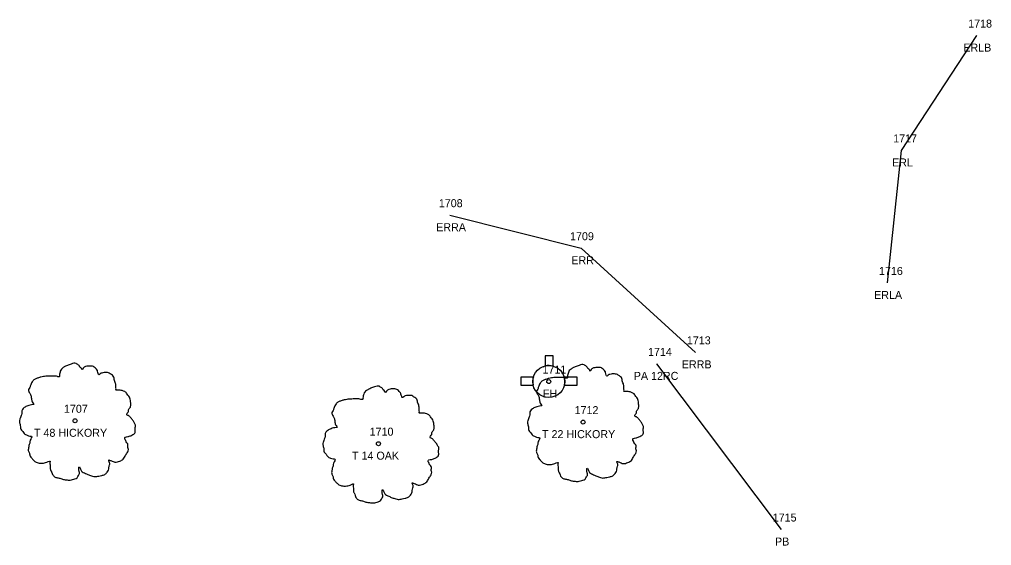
# Model space of a CAD drawing. Extents: x 1965822 to 1970313, y 1117097 to 1118160.
# Drawn here: x 1966667.7 to 1966789.1, y 1117381.5 to 1117447.2 of the extents above; entities that cross this region are included whole.
import ezdxf

# ---------------------------------------------------------------- set-up
doc = ezdxf.new("R2010")
doc.units = 0
for name, color, linetype in [('RD_EX_DR_Pipe', 7, 'Continuous'), ('RD_EX_DR_Pipe_txCode', 7, 'Continuous'), ('RD_EX_Road', 7, 'Continuous'), ('RD_EX_Road_txCode', 7, 'Continuous'), ('RD_EX_UT', 7, 'Continuous'), ('RD_EX_UT_txCode', 7, 'Continuous'), ('RD_EX_VEG', 7, 'Continuous'), ('RD_EX_VEG_txCode', 7, 'Continuous'), ('RD_SMD_Locator', 7, 'Continuous')]:
    doc.layers.add(name, color=color, linetype=linetype)

msp = doc.modelspace()

# ---------------------------------------------------------------- linework, layer by layer
at = {"layer": 'RD_EX_DR_Pipe'}
msp.add_line((1966747.3, 1117404.17), (1966762.88, 1117383.47), dxfattribs=at)
at = {"layer": 'RD_EX_Road'}
for points in [[(1966776.17, 1117414.28), (1966777.92, 1117430.84), (1966787.3, 1117445.19)], [(1966721.5, 1117422.75), (1966737.88, 1117418.62), (1966752.16, 1117405.61)]]:
    msp.add_lwpolyline(points, dxfattribs=at)
at = {"layer": 'RD_EX_UT'}
for p, q in [((1966733.38, 1117405.18), (1966733.38, 1117403.91)), ((1966734.38, 1117405.18), (1966733.38, 1117405.18)), ((1966734.38, 1117403.88), (1966734.38, 1117405.18)), ((1966731.92, 1117402.53), (1966730.37, 1117402.53)), ((1966730.37, 1117402.53), (1966730.37, 1117401.53)), ((1966737.37, 1117402.53), (1966735.76, 1117402.53)), ((1966737.37, 1117401.53), (1966737.37, 1117402.53)), ((1966730.37, 1117401.53), (1966731.89, 1117401.53)), ((1966735.79, 1117401.53), (1966737.37, 1117401.53))]:
    msp.add_line(p, q, dxfattribs=at)
for radius in [2, 0.25]:
    msp.add_circle((1966733.84, 1117401.96), radius, dxfattribs=at)
for start, end in [(74.2455, 103.2128), (163.3387, 192.315), (347.685, 16.6613)]:
    msp.add_arc((1966733.84, 1117401.96), 2, start, end, dxfattribs=at)
at = {"layer": 'RD_EX_VEG'}
for centre, radius in [((1966674.67, 1117397.06), 0.25), ((1966674.66, 1117397.04), 0.0001), ((1966738.13, 1117396.89), 0.25), ((1966738.12, 1117396.87), 0.0001), ((1966712.57, 1117394.2), 0.25), ((1966712.56, 1117394.18), 0.0001)]:
    msp.add_circle(centre, radius, dxfattribs=at)
for points in [[(1966674.81, 1117404.23), (1966674.51, 1117404.25), (1966674.18, 1117404.15), (1966673.93, 1117404.05), (1966673.71, 1117403.98), (1966673.48, 1117403.88), (1966673.18, 1117403.7), (1966672.96, 1117403.5), (1966672.83, 1117403.25), (1966672.78, 1117403.03), (1966672.73, 1117402.75), (1966672.73, 1117402.58), (1966672.61, 1117402.55), (1966672.46, 1117402.58), (1966672.21, 1117402.65), (1966671.96, 1117402.65), (1966671.71, 1117402.65), (1966671.36, 1117402.63), (1966671.01, 1117402.63), (1966670.73, 1117402.58), (1966670.41, 1117402.53), (1966670.03, 1117402.4), (1966669.68, 1117402.28), (1966669.38, 1117402.03), (1966669.13, 1117401.55), (1966669.01, 1117401.2), (1966668.86, 1117400.95), (1966669.01, 1117400.5), (1966669.18, 1117400.15), (1966669.21, 1117399.95), (1966669.28, 1117399.53), (1966669.38, 1117399.3), (1966669.51, 1117399.1), (1966669.43, 1117399.08), (1966669.06, 1117399.03), (1966668.76, 1117398.93), (1966668.33, 1117398.7), (1966668.11, 1117398.48), (1966668.01, 1117398.15), (1966667.98, 1117397.8), (1966667.88, 1117397.6), (1966667.81, 1117397.33), (1966667.78, 1117397.25), (1966667.73, 1117396.93), (1966667.83, 1117396.48), (1966667.86, 1117396.13), (1966667.98, 1117395.9), (1966668.13, 1117395.73), (1966668.31, 1117395.48), (1966668.71, 1117395.25), (1966669.03, 1117395.15), (1966669.23, 1117395.13), (1966669.06, 1117394.63), (1966669.01, 1117394.28), (1966668.88, 1117393.88), (1966668.88, 1117393.81), (1966668.83, 1117393.33), (1966668.98, 1117393.01), (1966669.06, 1117392.63), (1966669.23, 1117392.41), (1966669.51, 1117392.11), (1966669.83, 1117391.88), (1966670.33, 1117391.76), (1966670.73, 1117391.78), (1966671.31, 1117391.96), (1966671.56, 1117392.03), (1966671.53, 1117391.86), (1966671.56, 1117391.48), (1966671.56, 1117391.06), (1966671.71, 1117390.73), (1966671.81, 1117390.46), (1966671.96, 1117390.21), (1966672.28, 1117389.98), (1966672.68, 1117389.91), (1966673.11, 1117389.76), (1966673.56, 1117389.68), (1966674.06, 1117389.66), (1966674.66, 1117389.81), (1966674.93, 1117389.93), (1966675.03, 1117390.11), (1966675.23, 1117390.48), (1966675.18, 1117390.71), (1966675.21, 1117391.31), (1966675.31, 1117391.13), (1966675.48, 1117390.78), (1966675.98, 1117390.48), (1966676.38, 1117390.31), (1966676.86, 1117390.16), (1966677.16, 1117390.08), (1966677.63, 1117390.16), (1966678.01, 1117390.23), (1966678.38, 1117390.36), (1966678.68, 1117390.63), (1966678.85, 1117390.91), (1966678.9, 1117391.18), (1966678.98, 1117391.56), (1966679.03, 1117391.73)], [(1966679.03, 1117391.73), (1966678.95, 1117391.91), (1966678.9, 1117392.16), (1966678.98, 1117392.13), (1966679.15, 1117392.08), (1966679.43, 1117391.96), (1966679.65, 1117391.88), (1966679.98, 1117391.91), (1966680.25, 1117392.01), (1966680.7, 1117392.28), (1966680.98, 1117392.76), (1966681.25, 1117393.16), (1966681.33, 1117393.48), (1966681.28, 1117393.71), (1966681.25, 1117394.2), (1966681.05, 1117394.45), (1966681, 1117394.58), (1966680.9, 1117394.98), (1966680.98, 1117395.03), (1966681.25, 1117395.08), (1966681.63, 1117395.2), (1966681.9, 1117395.33), (1966682.13, 1117395.5), (1966682.2, 1117395.73), (1966682.18, 1117396.13), (1966682.23, 1117396.53), (1966682.15, 1117396.68), (1966682.05, 1117396.83), (1966681.98, 1117397.03), (1966681.83, 1117397.18), (1966681.73, 1117397.33), (1966681.63, 1117397.43), (1966681.5, 1117397.58), (1966681.33, 1117397.7), (1966681.18, 1117397.75), (1966681.13, 1117397.9), (1966681.28, 1117398.1), (1966681.33, 1117398.2), (1966681.35, 1117398.43), (1966681.58, 1117398.78), (1966681.63, 1117399.18), (1966681.58, 1117399.6), (1966681.53, 1117399.88), (1966681.38, 1117400.15), (1966681.18, 1117400.4), (1966681.05, 1117400.58), (1966680.88, 1117400.7), (1966680.55, 1117400.83), (1966680.3, 1117400.88), (1966679.95, 1117400.88), (1966679.75, 1117400.93), (1966679.78, 1117400.98), (1966679.78, 1117401.13), (1966679.78, 1117401.4), (1966679.7, 1117401.85), (1966679.55, 1117402.35), (1966679.55, 1117402.38), (1966679.45, 1117402.63), (1966679.23, 1117402.83), (1966679.05, 1117402.93), (1966678.85, 1117403.05), (1966678.6, 1117403.08), (1966678.3, 1117403.08), (1966678.03, 1117403.03), (1966677.83, 1117402.93), (1966677.66, 1117402.8), (1966677.58, 1117402.95), (1966677.48, 1117403.25), (1966677.43, 1117403.4), (1966677.28, 1117403.58), (1966677.06, 1117403.78), (1966676.61, 1117403.9), (1966675.98, 1117403.83), (1966675.68, 1117403.63), (1966675.53, 1117403.45), (1966675.48, 1117403.58), (1966675.28, 1117403.78), (1966675.18, 1117403.95), (1966675.01, 1117404.08), (1966674.86, 1117404.18), (1966674.76, 1117404.23)], [(1966738.26, 1117404.06), (1966737.96, 1117404.08), (1966737.64, 1117403.98), (1966737.39, 1117403.88), (1966737.16, 1117403.81), (1966736.94, 1117403.71), (1966736.64, 1117403.53), (1966736.41, 1117403.33), (1966736.29, 1117403.08), (1966736.24, 1117402.86), (1966736.19, 1117402.58), (1966736.19, 1117402.41), (1966736.06, 1117402.38), (1966735.91, 1117402.41), (1966735.66, 1117402.48), (1966735.41, 1117402.48), (1966735.16, 1117402.48), (1966734.81, 1117402.46), (1966734.46, 1117402.46), (1966734.19, 1117402.41), (1966733.86, 1117402.36), (1966733.49, 1117402.23), (1966733.14, 1117402.11), (1966732.84, 1117401.86), (1966732.59, 1117401.38), (1966732.46, 1117401.03), (1966732.31, 1117400.78), (1966732.46, 1117400.33), (1966732.64, 1117399.99), (1966732.66, 1117399.79), (1966732.74, 1117399.36), (1966732.84, 1117399.14), (1966732.96, 1117398.94), (1966732.89, 1117398.91), (1966732.51, 1117398.86), (1966732.21, 1117398.76), (1966731.79, 1117398.54), (1966731.56, 1117398.31), (1966731.46, 1117397.99), (1966731.44, 1117397.64), (1966731.34, 1117397.44), (1966731.26, 1117397.16), (1966731.24, 1117397.09), (1966731.19, 1117396.76), (1966731.29, 1117396.31), (1966731.31, 1117395.96), (1966731.44, 1117395.74), (1966731.59, 1117395.56), (1966731.76, 1117395.31), (1966732.16, 1117395.09), (1966732.49, 1117394.99), (1966732.69, 1117394.96), (1966732.51, 1117394.46), (1966732.46, 1117394.11), (1966732.34, 1117393.71), (1966732.34, 1117393.64), (1966732.29, 1117393.16), (1966732.44, 1117392.84), (1966732.51, 1117392.46), (1966732.69, 1117392.24), (1966732.96, 1117391.94), (1966733.29, 1117391.71), (1966733.79, 1117391.59), (1966734.19, 1117391.61), (1966734.76, 1117391.79), (1966735.01, 1117391.86), (1966734.99, 1117391.69), (1966735.01, 1117391.31), (1966735.01, 1117390.89), (1966735.16, 1117390.56), (1966735.26, 1117390.29), (1966735.41, 1117390.04), (1966735.74, 1117389.81), (1966736.14, 1117389.74), (1966736.56, 1117389.59), (1966737.01, 1117389.51), (1966737.51, 1117389.49), (1966738.11, 1117389.64), (1966738.39, 1117389.76), (1966738.49, 1117389.94), (1966738.69, 1117390.31), (1966738.64, 1117390.54), (1966738.66, 1117391.14), (1966738.76, 1117390.96), (1966738.94, 1117390.61), (1966739.44, 1117390.31), (1966739.84, 1117390.14), (1966740.31, 1117389.99), (1966740.61, 1117389.91), (1966741.08, 1117389.99), (1966741.46, 1117390.06), (1966741.83, 1117390.19), (1966742.13, 1117390.46), (1966742.31, 1117390.74), (1966742.36, 1117391.01), (1966742.43, 1117391.39), (1966742.48, 1117391.56)], [(1966742.48, 1117391.56), (1966742.41, 1117391.74), (1966742.36, 1117391.99), (1966742.43, 1117391.96), (1966742.61, 1117391.91), (1966742.88, 1117391.79), (1966743.11, 1117391.71), (1966743.43, 1117391.74), (1966743.71, 1117391.84), (1966744.16, 1117392.11), (1966744.43, 1117392.59), (1966744.71, 1117392.99), (1966744.78, 1117393.31), (1966744.73, 1117393.54), (1966744.71, 1117394.04), (1966744.51, 1117394.29), (1966744.46, 1117394.41), (1966744.36, 1117394.81), (1966744.43, 1117394.86), (1966744.71, 1117394.91), (1966745.08, 1117395.04), (1966745.36, 1117395.16), (1966745.58, 1117395.34), (1966745.66, 1117395.56), (1966745.63, 1117395.96), (1966745.68, 1117396.36), (1966745.61, 1117396.51), (1966745.51, 1117396.66), (1966745.43, 1117396.86), (1966745.28, 1117397.01), (1966745.18, 1117397.16), (1966745.08, 1117397.26), (1966744.96, 1117397.41), (1966744.78, 1117397.54), (1966744.63, 1117397.59), (1966744.58, 1117397.74), (1966744.73, 1117397.94), (1966744.78, 1117398.04), (1966744.81, 1117398.26), (1966745.03, 1117398.61), (1966745.08, 1117399.01), (1966745.03, 1117399.44), (1966744.98, 1117399.71), (1966744.83, 1117399.99), (1966744.63, 1117400.23), (1966744.51, 1117400.41), (1966744.33, 1117400.53), (1966744.01, 1117400.66), (1966743.76, 1117400.71), (1966743.41, 1117400.71), (1966743.21, 1117400.76), (1966743.23, 1117400.81), (1966743.23, 1117400.96), (1966743.23, 1117401.23), (1966743.16, 1117401.68), (1966743.01, 1117402.18), (1966743.01, 1117402.21), (1966742.91, 1117402.46), (1966742.68, 1117402.66), (1966742.51, 1117402.76), (1966742.31, 1117402.88), (1966742.06, 1117402.91), (1966741.76, 1117402.91), (1966741.48, 1117402.86), (1966741.28, 1117402.76), (1966741.11, 1117402.63), (1966741.03, 1117402.78), (1966740.93, 1117403.08), (1966740.88, 1117403.23), (1966740.73, 1117403.41), (1966740.51, 1117403.61), (1966740.06, 1117403.73), (1966739.44, 1117403.66), (1966739.14, 1117403.46), (1966738.99, 1117403.28), (1966738.94, 1117403.41), (1966738.74, 1117403.61), (1966738.64, 1117403.78), (1966738.46, 1117403.91), (1966738.31, 1117404.01), (1966738.21, 1117404.06)], [(1966712.7, 1117401.37), (1966712.4, 1117401.4), (1966712.08, 1117401.3), (1966711.83, 1117401.2), (1966711.6, 1117401.12), (1966711.38, 1117401.02), (1966711.08, 1117400.85), (1966710.85, 1117400.65), (1966710.73, 1117400.4), (1966710.68, 1117400.17), (1966710.63, 1117399.9), (1966710.63, 1117399.72), (1966710.5, 1117399.7), (1966710.35, 1117399.72), (1966710.1, 1117399.8), (1966709.85, 1117399.8), (1966709.6, 1117399.8), (1966709.25, 1117399.77), (1966708.9, 1117399.77), (1966708.63, 1117399.72), (1966708.3, 1117399.67), (1966707.93, 1117399.55), (1966707.58, 1117399.42), (1966707.28, 1117399.17), (1966707.03, 1117398.7), (1966706.9, 1117398.35), (1966706.75, 1117398.1), (1966706.9, 1117397.65), (1966707.08, 1117397.3), (1966707.1, 1117397.1), (1966707.18, 1117396.67), (1966707.28, 1117396.45), (1966707.4, 1117396.25), (1966707.33, 1117396.22), (1966706.95, 1117396.17), (1966706.65, 1117396.07), (1966706.23, 1117395.85), (1966706, 1117395.62), (1966705.9, 1117395.3), (1966705.88, 1117394.95), (1966705.78, 1117394.75), (1966705.7, 1117394.47), (1966705.68, 1117394.4), (1966705.63, 1117394.07), (1966705.73, 1117393.62), (1966705.75, 1117393.27), (1966705.88, 1117393.05), (1966706.03, 1117392.87), (1966706.2, 1117392.62), (1966706.6, 1117392.4), (1966706.93, 1117392.3), (1966707.13, 1117392.27), (1966706.95, 1117391.77), (1966706.9, 1117391.42), (1966706.78, 1117391.02), (1966706.78, 1117390.95), (1966706.73, 1117390.48), (1966706.88, 1117390.15), (1966706.95, 1117389.78), (1966707.13, 1117389.55), (1966707.4, 1117389.25), (1966707.73, 1117389.03), (1966708.23, 1117388.9), (1966708.63, 1117388.93), (1966709.2, 1117389.1), (1966709.45, 1117389.18), (1966709.43, 1117389), (1966709.45, 1117388.63), (1966709.45, 1117388.2), (1966709.6, 1117387.88), (1966709.7, 1117387.6), (1966709.85, 1117387.35), (1966710.18, 1117387.13), (1966710.58, 1117387.05), (1966711, 1117386.9), (1966711.45, 1117386.83), (1966711.95, 1117386.8), (1966712.55, 1117386.95), (1966712.83, 1117387.08), (1966712.93, 1117387.25), (1966713.12, 1117387.63), (1966713.07, 1117387.85), (1966713.1, 1117388.45), (1966713.2, 1117388.28), (1966713.37, 1117387.93), (1966713.87, 1117387.63), (1966714.27, 1117387.45), (1966714.75, 1117387.3), (1966715.05, 1117387.23), (1966715.52, 1117387.3), (1966715.9, 1117387.38), (1966716.27, 1117387.5), (1966716.57, 1117387.78), (1966716.75, 1117388.05), (1966716.8, 1117388.33), (1966716.87, 1117388.7), (1966716.92, 1117388.88)], [(1966716.92, 1117388.88), (1966716.85, 1117389.05), (1966716.8, 1117389.3), (1966716.87, 1117389.28), (1966717.05, 1117389.23), (1966717.32, 1117389.1), (1966717.55, 1117389.03), (1966717.87, 1117389.05), (1966718.15, 1117389.15), (1966718.6, 1117389.43), (1966718.87, 1117389.9), (1966719.15, 1117390.3), (1966719.22, 1117390.63), (1966719.17, 1117390.85), (1966719.15, 1117391.35), (1966718.95, 1117391.6), (1966718.9, 1117391.72), (1966718.8, 1117392.12), (1966718.87, 1117392.17), (1966719.15, 1117392.22), (1966719.52, 1117392.35), (1966719.8, 1117392.47), (1966720.02, 1117392.65), (1966720.1, 1117392.87), (1966720.07, 1117393.27), (1966720.12, 1117393.67), (1966720.05, 1117393.82), (1966719.95, 1117393.97), (1966719.87, 1117394.17), (1966719.72, 1117394.32), (1966719.62, 1117394.47), (1966719.52, 1117394.57), (1966719.4, 1117394.72), (1966719.22, 1117394.85), (1966719.07, 1117394.9), (1966719.02, 1117395.05), (1966719.17, 1117395.25), (1966719.22, 1117395.35), (1966719.25, 1117395.57), (1966719.47, 1117395.92), (1966719.52, 1117396.32), (1966719.47, 1117396.75), (1966719.42, 1117397.02), (1966719.27, 1117397.3), (1966719.07, 1117397.55), (1966718.95, 1117397.72), (1966718.77, 1117397.85), (1966718.45, 1117397.97), (1966718.2, 1117398.02), (1966717.85, 1117398.02), (1966717.65, 1117398.07), (1966717.67, 1117398.12), (1966717.67, 1117398.27), (1966717.67, 1117398.55), (1966717.6, 1117399), (1966717.45, 1117399.5), (1966717.45, 1117399.52), (1966717.35, 1117399.77), (1966717.12, 1117399.97), (1966716.95, 1117400.07), (1966716.75, 1117400.2), (1966716.5, 1117400.22), (1966716.2, 1117400.22), (1966715.92, 1117400.17), (1966715.72, 1117400.07), (1966715.55, 1117399.95), (1966715.47, 1117400.1), (1966715.37, 1117400.4), (1966715.32, 1117400.55), (1966715.17, 1117400.72), (1966714.95, 1117400.92), (1966714.5, 1117401.05), (1966713.87, 1117400.97), (1966713.57, 1117400.77), (1966713.42, 1117400.6), (1966713.37, 1117400.72), (1966713.17, 1117400.92), (1966713.07, 1117401.1), (1966712.9, 1117401.22), (1966712.75, 1117401.32), (1966712.65, 1117401.37)]]:
    msp.add_spline(points, degree=3, dxfattribs=at)
at = {"layer": 'RD_SMD_Locator'}
for centre in [(1966787.3, 1117445.19), (1966777.92, 1117430.84), (1966721.5, 1117422.75), (1966737.88, 1117418.62), (1966776.17, 1117414.28), (1966752.16, 1117405.61), (1966747.3, 1117404.17), (1966762.88, 1117383.47)]:
    msp.add_circle(centre, 0.001, dxfattribs=at)

# ---------------------------------------------------------------- texts
at = {"layer": 'RD_EX_DR_Pipe_txCode'}
for s, p in [('1714', (1966746.24, 1117405.17)), ('PA 12RC', (1966744.46, 1117402.17)), ('1715', (1966761.82, 1117384.47)), ('PB', (1966762.1, 1117381.47))]:
    msp.add_text(s, height=1, dxfattribs=at).set_placement(p)
at = {"layer": 'RD_EX_Road_txCode'}
for s, p in [('1718', (1966786.23, 1117446.19)), ('ERLB', (1966785.62, 1117443.19)), ('1717', (1966776.86, 1117431.84)), ('ERL', (1966776.72, 1117428.84)), ('1708', (1966720.11, 1117423.75)), ('ERRA', (1966719.78, 1117420.75)), ('1709', (1966736.5, 1117419.62)), ('ERR', (1966736.66, 1117416.62)), ('1716', (1966775.09, 1117415.28)), ('ERLA', (1966774.48, 1117412.28)), ('1713', (1966751.09, 1117406.61)), ('ERRB', (1966750.46, 1117403.61))]:
    msp.add_text(s, height=1, dxfattribs=at).set_placement(p)
at = {"layer": 'RD_EX_UT_txCode'}
for s, p in [('1711', (1966733.06, 1117402.96)), ('FH', (1966733.11, 1117399.96))]:
    msp.add_text(s, height=1, dxfattribs=at).set_placement(p)
at = {"layer": 'RD_EX_VEG_txCode'}
for s, p in [('1707', (1966673.29, 1117398.06)), ('1712', (1966737.07, 1117397.89)), ('T 48 HICKORY', (1966669.54, 1117395.06)), ('1710', (1966711.47, 1117395.2)), ('T 22 HICKORY', (1966733, 1117394.89)), ('T 14 OAK', (1966709.27, 1117392.2))]:
    msp.add_text(s, height=1, dxfattribs=at).set_placement(p)

doc.saveas('drawing.dxf')
